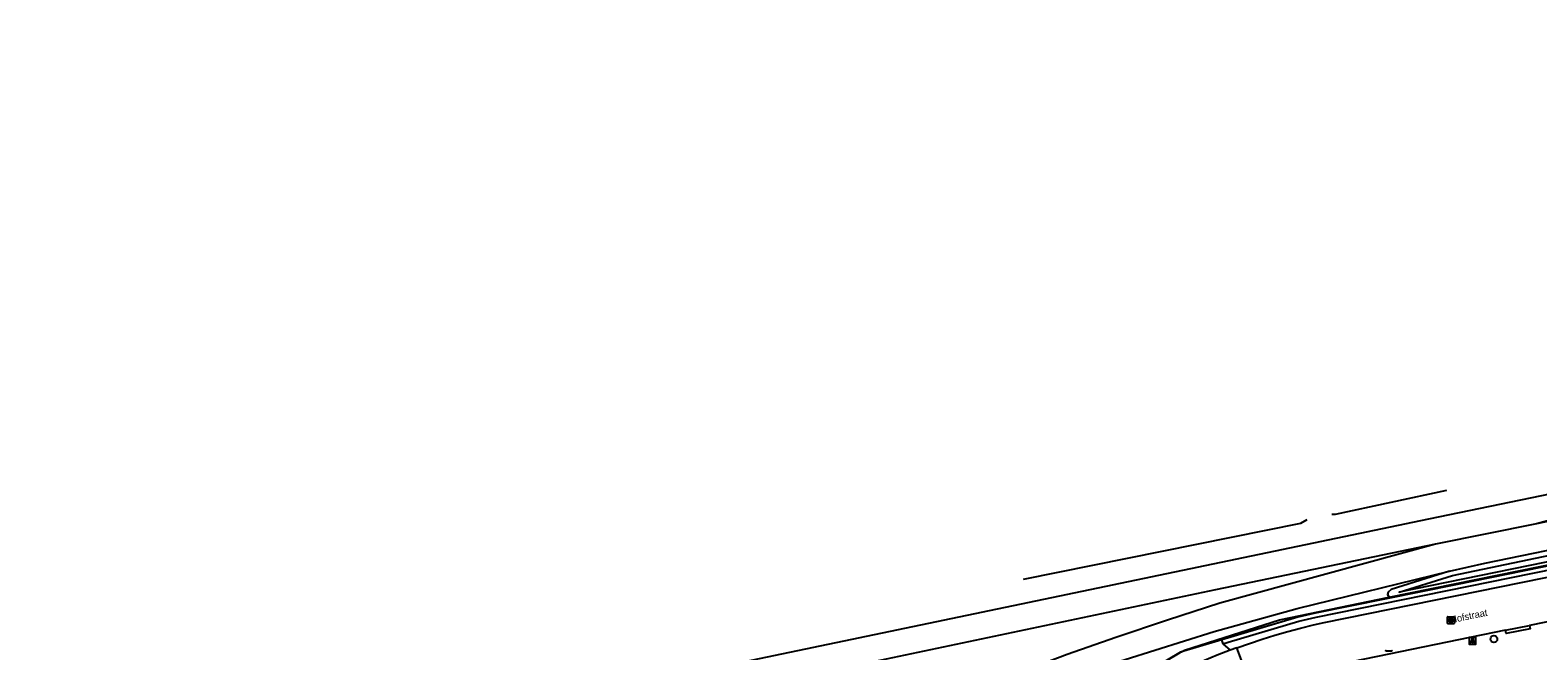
# Model space of a CAD drawing. Extents: x 162990 to 165007, y 383433 to 384336.
# Drawn here: x 163237.1 to 163454.1, y 384036 to 384125.4 of the extents above; entities that cross this region are included whole.
import ezdxf

# ---------------------------------------------------------------- set-up
doc = ezdxf.new("R2010")
doc.units = 0
for name, color, linetype in [('IMGEO_Berm_groen', 7, 'Continuous'), ('IMGEO_Boom', 7, 'Continuous'), ('IMGEO_Grasland_overig', 7, 'Continuous'), ('IMGEO_Greppel_droge_sloot', 7, 'Continuous'), ('IMGEO_Haag', 7, 'Continuous'), ('IMGEO_Hek', 7, 'Continuous'), ('IMGEO_Kolk', 7, 'Continuous'), ('IMGEO_Lichtpunt', 7, 'Continuous'), ('IMGEO_Openbare_ruimte_label', 7, 'Continuous'), ('IMGEO_Rijbaan_lokaal_gesloten', 7, 'Continuous'), ('IMGEO_Rijbaan_lokaal_open', 7, 'Continuous'), ('IMGEO_Rioolput', 7, 'Continuous'), ('IMGEO_Spoor', 7, 'Continuous'), ('IMGEO_Spoorbaan_halfverhard', 7, 'Continuous'), ('IMGEO_Voetpad_open', 7, 'Continuous')]:
    doc.layers.add(name, color=color, linetype=linetype)

msp = doc.modelspace()

# ---------------------------------------------------------------- linework, layer by layer
at = {"layer": 'IMGEO_Berm_groen'}
for points in [[(163432.67, 384043.74), (163479.46, 384053.27)], [(163274.5, 383977.63), (163278.73, 383980.12), (163284.27, 383982.86), (163294.54, 383987.66), (163296.98, 383988.8), (163323.04, 383998.11), (163383.18, 384024.21), (163402.58, 384035.79), (163402.67, 384035.84), (163402.81, 384035.89), (163403.25, 384036.14), (163416.88, 384040.51), (163432.67, 384043.74)], [(163408.73, 384037.02), (163409.81, 384036.1)]]:
    msp.add_lwpolyline(points, dxfattribs=at)
at = {"layer": 'IMGEO_Boom'}
msp.add_circle((163447.77, 384037.72), 0.489, dxfattribs=at)
at = {"layer": 'IMGEO_Grasland_overig'}
msp.add_lwpolyline([(163441.36, 384047.51), (163432.97, 384044.84), (163432.57, 384044.48), (163432.44, 384044.12), (163432.67, 384043.74)], dxfattribs=at)
at = {"layer": 'IMGEO_Greppel_droge_sloot'}
msp.add_lwpolyline([(163478.56, 384053.53), (163434.12, 384044.48), (163441.81, 384046.87), (163459.26, 384050.53), (163478.26, 384054.35), (163478.49, 384054.15), (163478.58, 384053.94), (163478.56, 384053.53)], dxfattribs=at)
at = {"layer": 'IMGEO_Haag'}
for points in [[(163408.73, 384037.02), (163409.52, 384037.26), (163419.71, 384040.29), (163422.16, 384040.85), (163459.77, 384048.49), (163651.74, 384088.02), (163830.89, 384125.39)], [(163481.62, 384053.54), (163459.65, 384049.07), (163442.26, 384045.54), (163422.03, 384041.44), (163419.56, 384040.87), (163408.56, 384037.6), (163408.73, 384037.02)]]:
    msp.add_lwpolyline(points, dxfattribs=at)
at = {"layer": 'IMGEO_Hek'}
for points in [[(163459.65, 384049.07), (163442.26, 384045.54)], [(163442.26, 384045.54), (163422.03, 384041.44), (163419.56, 384040.87), (163402.67, 384035.84)], [(163254.53, 383975.15), (163255.17, 383979.4), (163274.5, 383977.63), (163274.64, 383977.71), (163276.58, 383978.8), (163278.72, 383980.18), (163283.21, 383982.5), (163290.07, 383985.7), (163294.6, 383987.8), (163297.16, 383988.85), (163299.29, 383989.75), (163301.68, 383990.54), (163315.91, 383995.57), (163322.99, 383998.13), (163325.3, 383999.08), (163329.99, 384001.1), (163341.56, 384006.06), (163350.75, 384010.13), (163366.94, 384017.17), (163383.12, 384024.21), (163402.7, 384035.89), (163408.95, 384037.88)]]:
    msp.add_lwpolyline(points, dxfattribs=at)
at = {"layer": 'IMGEO_Kolk'}
msp.add_line((163432.24, 384036.02), (163433.1, 384036.02), dxfattribs=at)
msp.add_lwpolyline([(163432.24, 384036.02), (163433.1, 384036.02)], dxfattribs=at)
for centre, start, end in [((163432.24, 384035.95), 91.552, 178.448), ((163432.24, 384035.95), 91.552, 178.448), ((163433.09, 384035.95), 1.552, 88.448), ((163433.09, 384035.95), 1.552, 88.448)]:
    msp.add_arc(centre, 0.0765, start, end, dxfattribs=at)
at = {"layer": 'IMGEO_Lichtpunt'}
for p, q in [((163444.19, 384037.86), (163444.19, 384037.06)), ((163444.19, 384037.86), (163444.19, 384037.06)), ((163445.09, 384037.96), (163444.29, 384037.96)), ((163445.09, 384037.96), (163444.29, 384037.96)), ((163444.29, 384036.96), (163445.09, 384036.96)), ((163444.29, 384036.96), (163445.09, 384036.96)), ((163445.19, 384037.06), (163445.19, 384037.86)), ((163445.19, 384037.06), (163445.19, 384037.86))]:
    msp.add_line(p, q, dxfattribs=at)
for points in [[(163444.57, 384037.53), (163444.61, 384037.5), (163444.42, 384037.24), (163444.38, 384037.26), (163444.57, 384037.53)], [(163444.67, 384037.48), (163444.72, 384037.48), (163444.72, 384037.16), (163444.67, 384037.16), (163444.67, 384037.48)], [(163444.78, 384037.5), (163444.82, 384037.53), (163445, 384037.26), (163444.97, 384037.24), (163444.78, 384037.5)]]:
    msp.add_lwpolyline(points, dxfattribs=at)
msp.add_circle((163444.69, 384037.66), 0.0994, dxfattribs=at)
for centre, start, end in [((163444.29, 384037.86), 90, 180), ((163444.29, 384037.86), 90, 180), ((163444.29, 384037.06), 180, 270), ((163444.29, 384037.06), 180, 270), ((163445.09, 384037.86), 0, 90), ((163445.09, 384037.86), 0, 90), ((163445.09, 384037.06), 270, 0), ((163445.09, 384037.06), 270, 360)]:
    msp.add_arc(centre, 0.0946, start, end, dxfattribs=at)
at = {"layer": 'IMGEO_Rijbaan_lokaal_gesloten'}
for points in [[(163410.77, 384036.46), (163412.58, 384037.1), (163414.4, 384037.71), (163416.24, 384038.28), (163418.08, 384038.82), (163419.94, 384039.31), (163421.81, 384039.77), (163423.33, 384040.11), (163470.86, 384049.76)], [(163472.1, 384043.61), (163452.88, 384039.68)], [(163449.45, 384038.98), (163427.53, 384034.51)], [(163449.45, 384038.98), (163452.88, 384039.68)]]:
    msp.add_lwpolyline(points, dxfattribs=at)
at = {"layer": 'IMGEO_Rijbaan_lokaal_open'}
for points in [[(163410.77, 384036.46), (163409.81, 384036.1)], [(163412.91, 384030.74), (163410.77, 384036.46)], [(163409.81, 384036.1), (163407.95, 384035.4), (163406.11, 384034.65), (163404.28, 384033.87), (163403.71, 384033.59)]]:
    msp.add_lwpolyline(points, dxfattribs=at)
at = {"layer": 'IMGEO_Rioolput'}
for p, q in [((163441.08, 384040), (163441.08, 384040.85)), ((163441.16, 384040.92), (163442.01, 384040.92)), ((163442.08, 384040.85), (163442.08, 384040)), ((163442.01, 384039.92), (163441.16, 384039.92)), ((163441.57, 384040.7), (163441.6, 384040.7)), ((163441.59, 384040.14), (163441.57, 384040.14))]:
    msp.add_line(p, q, dxfattribs=at)
for points in [[(163441.08, 384040), (163441.08, 384040.85)], [(163441.16, 384040.92), (163442.01, 384040.92)], [(163442.08, 384040.85), (163442.08, 384040)], [(163442.01, 384039.92), (163441.16, 384039.92)], [(163441.67, 384040.62), (163441.42, 384040.62), (163441.42, 384040.22)], [(163441.42, 384040.22), (163441.54, 384040.22), (163441.54, 384040.38), (163441.56, 384040.38)], [(163441.6, 384040.54), (163441.54, 384040.54), (163441.54, 384040.46)], [(163441.54, 384040.46), (163441.6, 384040.46)], [(163441.6, 384040.35), (163441.67, 384040.22), (163441.81, 384040.22), (163441.75, 384040.35)]]:
    msp.add_lwpolyline(points, dxfattribs=at)
for centre, radius, start, end in [((163441.16, 384040.85), 0.0765, 91.552, 178.448), ((163441.16, 384040.85), 0.0765, 91.552, 178.448), ((163442.01, 384040.85), 0.0765, 1.552, 88.448), ((163442.01, 384040.85), 0.0765, 1.552, 88.448), ((163441.16, 384040), 0.0765, 181.552, 268.448), ((163441.16, 384040), 0.0765, 181.552, 268.448), ((163441.55, 384040.33), 0.0533, 26.0293, 88.6989), ((163441.6, 384040.44), 0.0964, 77.0061, 93.1865), ((163441.58, 384040.65), 0.19, 274.7715, 282.9687), ((163441.62, 384040.5), 0.0378, 276.6634, 79.6772), ((163441.67, 384040.51), 0.109, 350.3612, 89.416), ((163441.67, 384040.51), 0.112, 277.5842, 350.9817), ((163441.65, 384040.29), 0.108, 29.5134, 73.7905), ((163442.01, 384040), 0.0765, 271.552, 358.448), ((163442.01, 384040), 0.0765, 271.552, 358.448)]:
    msp.add_arc(centre, radius, start, end, dxfattribs=at)
for centre, major_axis, ratio, start_param, end_param in [((163441.57, 384040.42), (-0.387, 0.002), 0.722429, 4.712389, 7.853982), ((163441.59, 384040.42), (-0.39, 0.002), 0.717154, 1.570796, 4.712389)]:
    msp.add_ellipse(centre, major_axis=major_axis, ratio=ratio, start_param=start_param, end_param=end_param, dxfattribs=at)
at = {"layer": 'IMGEO_Spoor'}
for points in [[(163482.5, 384064.12), (163438.35, 384055), (163304.28, 384027.02), (163290.65, 384024.26), (163275.14, 384021.27), (163261.91, 384018.85), (163250.28, 384016.87), (163239.03, 384015.08), (163225.05, 384013.19), (163210.68, 384011.42), (163197.57, 384010.04), (163186.31, 384009.05), (163170.78, 384007.96), (163157.74, 384007.24), (163145.35, 384006.77), (163136.4, 384006.59), (163127.53, 384006.53), (163114.97, 384006.67), (163093.3, 384007.27), (163079.79, 384007.9), (163066.12, 384008.71), (163050.35, 384009.85), (163020.29, 384012.34), (163007.93, 384013.45)], [(163482.18, 384062.04), (163453.9, 384054.29)], [(163482.89, 384060.37), (163453.9, 384054.29)], [(163453.9, 384054.29), (163439.34, 384051.38)], [(163439.34, 384051.38), (163407.71, 384044.79)], [(163439.34, 384051.38), (163408.32, 384042.87)], [(163407.71, 384044.79), (163319.26, 384026.2), (163284.13, 384019.05), (163265.69, 384015.56), (163249.75, 384012.76), (163238.32, 384010.85), (163218.99, 384008.12), (163175.89, 384003.97), (163154.95, 384002.74), (163133.87, 384002.08), (163105.01, 384002.11), (163077.27, 384002.8), (163012.33, 384005.28)], [(163408.32, 384042.87), (163400.77, 384040.46), (163393.36, 384037.96), (163386.36, 384035.48), (163379.62, 384032.97), (163369.23, 384028.84), (163351.98, 384021.6), (163336.71, 384015.07), (163328.56, 384011.74), (163316.71, 384007.3), (163310.21, 384005.06), (163302.04, 384002.4)]]:
    msp.add_lwpolyline(points, dxfattribs=at)
at = {"layer": 'IMGEO_Spoorbaan_halfverhard'}
for points in [[(163440.92, 384059.12), (163424.92, 384055.66), (163424.44, 384055.65)], [(163420.83, 384054.89), (163419.92, 384054.35), (163380.02, 384046.29)], [(163441.36, 384047.51), (163446.46, 384048.64), (163478.22, 384055.18)], [(163230.82, 383983.33), (163242.04, 383984.31), (163251.58, 383985.84), (163274.36, 383990.58), (163280.68, 383991.96), (163296.12, 383996.4), (163314.07, 384002.16), (163315.93, 384002.46), (163317.42, 384003.3), (163318.91, 384004.28), (163335.39, 384010.06), (163360.95, 384020.9), (163385.57, 384031.62), (163387.41, 384031.71), (163388.82, 384032.32), (163390.43, 384033.42), (163407.52, 384038.82), (163419.45, 384042.13), (163441.36, 384047.51)]]:
    msp.add_lwpolyline(points, dxfattribs=at)
at = {"layer": 'IMGEO_Voetpad_open'}
msp.add_lwpolyline([(163452.88, 384039.68), (163452.98, 384039.2), (163449.53, 384038.54), (163449.45, 384038.98)], dxfattribs=at)

# ---------------------------------------------------------------- texts
at = {"layer": 'IMGEO_Openbare_ruimte_label'}
msp.add_text('Hofstraat', height=1, rotation=11.5907, dxfattribs=at).set_placement((163441.59, 384039.99))

doc.saveas('drawing.dxf')
